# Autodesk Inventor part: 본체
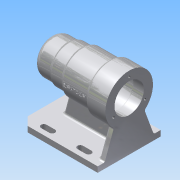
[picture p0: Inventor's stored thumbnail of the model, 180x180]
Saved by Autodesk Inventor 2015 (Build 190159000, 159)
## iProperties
Created: 2017-09
Part Number: 본체
Material: 알루미늄 6061
Document SubType Name: Modeling
Designer: Administrator
Density: 2.7 g/cm^3
Appearance: 알루미늄 - 평지
Author: Administrator
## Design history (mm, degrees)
sketch "스케치1"
  geometry: L1 (-133.636, 0)-(143, 0); L2 (112, 34)-(112, 0); L3 (112, 34)-(84, 34); L4 (84, 34)-(84, 30); L5 (84, 30)-(45, 30); L6 (45, 30)-(45, 27); L7 (45, 27)-(25, 27); L8 (0, 0)-(112, 0); L9 (25, 27)-(25, 25); L10 (25, 25)-(0, 25); L11 (0, 25)-(0, 0)
  constraints: 23 end point, 5 perpendicular, 3 horizontal, 3 vertical, 1 point on line
  dimensions: "d1" = 68 diameter of L3 L1; "d2" = 112 distance between parallel lines of L2 L11; "d3" = 60 diameter of L5 L1; "d4" = 54 diameter of L7 L1; "d5" = 50 diameter of L10 L1; "d6" = 84 distance between parallel lines of L4 L11; "d7" = 45 distance between parallel lines of L6 L11; "d8" = 25 distance between parallel lines of L9 L11
revolve "회전1" sketch "스케치1" stored, may be unused: angle "d9" = 90 deg
sketch "스케치2"
  geometry: L1 (0, -25)-(0, 25) reference; L2 (0, 25)-(25, 25) reference; L3 (25, 25)-(25, 27) reference; L4 (25, 27)-(45, 27) reference; L5 (45, 27)-(45, 30) reference; L6 (45, 30)-(84, 30) reference; L7 (84, 30)-(84, 34) reference; L8 (84, 34)-(112, 34) reference; L9 (112, 34)-(112, -34) reference; L10 (112, -34)-(84, -34) reference; L11 (84, -34)-(84, -30) reference; L12 (84, -30)-(45, -30) reference; L13 (45, -30)-(45, -27) reference; L14 (45, -27)-(25, -27) reference; L15 (25, -27)-(25, -25) reference; L16 (25, -25)-(0, -25) reference; L17 (-42, 0)-(152.04, 0); L18 (31, 17.5)-(31, 21); L19 (31, 21)-(43, 21); L20 (43, 21)-(43, 24); L21 (43, 24)-(97, 24); L22 (97, 24)-(97, 21); L23 (97, 21)-(112, 21); L24 (31, 17.5)-(13, 17.5); L25 (13, 17.5)-(13, 16); L26 (13, 16)-(9, 16); L27 (9, 16)-(9, 10.5); L28 (9, 10.5)-(6, 10.5); L29 (6, 10.5)-(6, 0); L30 (112, 21)-(112, 0); L31 (112, -34)-(112, 34) reference; L32 (6, 0)-(112, 0); 2 further points
  constraints: 30 end point, 9 perpendicular, 3 point on line, 3 vertical, 2 horizontal, 2 midpoint
  dimensions: "d10" = 42 diameter of L23 L17; "d11" = 15 distance of L22.end L23.end; "d12" = 48 diameter of L21 L17; "d13" = 54 distance of L20.end L21.end; "d14" = 42 diameter of L19 L17; "d15" = 12 distance between parallel lines of L20 L18; "d16" = 35 diameter of L24 L17; "d17" = 18 distance of L18.start L24.end; "d18" = 4 distance of L25.end L26.end; "d19" = 32 diameter of L26 L17; "d20" = 21 diameter of L28 L17; "d21" = 3 distance of L27.end L28.end
revolve "회전2" sketch "스케치2" stored, may be unused: angle "d22" = 90 deg
sketch "스케치3"
  geometry: L1 (-45, -62)-(45, -62); L2 (45, -62)-(45, -70); L3 (45, -70)-(-45, -70); L4 (-45, -70)-(-45, -62); C1 r 21 at (0, 0) reference; 1 further point
  constraints: 8 end point, 2 parallel, 1 horizontal, 1 midpoint, 1 perpendicular, 1 vertical alignment
  dimensions: "d23" = 8 distance between parallel lines of L3 L1; "d24" = 70 distance from line of L3 C1.centre; "d25" = 90 distance of L2.end L3.end
extrude "돌출1" join sketch "스케치3" distance "d26" = 112; taper "d27" = 0 deg
sketch "스케치4"
  geometry: L1 (21.067, -23.72)-(35.644, -63.77); L2 (35.644, -63.77)-(-35.644, -63.77); L3 (-35.644, -63.77)-(-21.067, -23.72); L4 (-21.067, -23.72)-(21.067, -23.72); L5 (-45, -62)-(45, -62) reference; L6 (-45, -70)-(-45, -62) reference; C1 r 21 at (0, 0) reference; 4 further points
  constraints: 8 end point, 4 point on line, 2 horizontal, 2 midpoint, 2 vertical alignment
  dimensions: "d28" = 110 deg angle of L5 L1; "d29" = 10 distance from line of L6 point (-35, -62)
extrude "돌출2" join sketch "스케치4" distance "d30" = 8; taper "d31" = 0 deg
sketch "스케치5"
  geometry: L1 (0, -25)-(0, 25) reference; L2 (0, 25)-(25, 25) reference; L3 (25, 25)-(25, 27) reference; L4 (25, 27)-(45, 27) reference; L5 (45, 27)-(45, 30) reference; L6 (45, 30)-(84, 30) reference; L7 (84, 30)-(84, 34) reference; L8 (84, 34)-(112, 34) reference; L9 (112, 34)-(112, 21) reference; L10 (112, 21)-(97, 21) reference; L11 (97, 21)-(97, 24) reference; L12 (97, 24)-(43, 24) reference; L13 (43, 24)-(43, 21) reference; L14 (43, 21)-(31, 21) reference; L15 (31, 21)-(31, 17.5) reference; L16 (31, 17.5)-(13, 17.5) reference; L17 (13, 17.5)-(13, 16) reference; L18 (13, 16)-(9, 16) reference; L19 (9, 16)-(9, 10.5) reference; L20 (9, 10.5)-(6, 10.5) reference; L21 (6, 10.5)-(6, -10.5) reference; L22 (6, -10.5)-(9, -10.5) reference; L23 (9, -10.5)-(9, -16) reference; L24 (9, -16)-(13, -16) reference; L25 (13, -16)-(13, -17.5) reference; L26 (13, -17.5)-(31, -17.5) reference; L27 (31, -17.5)-(31, -21) reference; L28 (31, -21)-(43, -21) reference; L29 (43, -21)-(43, -24) reference; L30 (43, -24)-(97, -24) reference; L31 (97, -24)-(97, -21) reference; L32 (97, -21)-(112, -21) reference; L33 (112, -21)-(112, -70) reference; L34 (112, -70)-(0, -70) reference; L35 (0, -70)-(0, -62) reference; L36 (0, -62)-(104, -62) reference; L37 (104, -62)-(104, -34) reference; L38 (104, -34)-(84, -34) reference; L39 (84, -34)-(84, -30) reference; L40 (84, -30)-(45, -30) reference; L41 (45, -30)-(45, -27) reference; L42 (45, -27)-(25, -27) reference; L43 (25, -27)-(25, -25) reference; L44 (25, -25)-(0, -25) reference; L45 (21.226, -64.887)-(31.878, -25.133); L46 (21.226, -64.887)-(107, -64.887); L47 (107, -64.887)-(107, -25.133); L48 (107, -25.133)-(31.878, -25.133); 2 further points
  constraints: 8 end point, 2 horizontal, 2 point on line, 1 vertical
  dimensions: "d32" = 105 deg angle of L45 L36; "d33" = 22 distance from line of L35 point (22, -62)
extrude "돌출3" join sketch "스케치5" stored distance "d34" = 8; taper "d35" = 0 deg
chamfer "모따기1" distance "d36" = 12; stored, may be unused: second distance "d37" = 2, angle "d38" = 45 deg
sketch "스케치6"
  geometry: L1 (0, 0)-(0, 10) reference; L2 (-88, 11)-(-76, 11); L3 (-88, 7)-(-76, 7); L4 (-76, 15)-(-88, 15); L5 (-36, 11)-(-24, 11); L6 (-36, 7)-(-24, 7); L7 (-24, 15)-(-36, 15); A1 r 4 centre (-88, 11) between (-88, 15) and (-88, 7); A2 r 4 centre (-76, 11) between (-76, 7) and (-76, 15); A3 r 4 centre (-36, 11) between (-36, 15) and (-36, 7); A4 r 4 centre (-24, 11) between (-24, 7) and (-24, 15); 3 further points
  constraints: 16 end point, 8 point on circle, 8 tangent, 4 centre point, 2 horizontal, 2 midpoint, 2 parallel, 1 horizontal alignment
  dimensions: "d39" = 4 radius of A1; "d40" = 12 distance of L2.start L2.end; "d41" = 34 distance from line of L2 point (-112, 45); "d42" = 12 distance of L5.start L5.end; "d43" = 4 radius of A3; "d44" = 24 distance from line of L1 L5.end; "d45" = 40 distance of L2.end L5.start
extrude "돌출4" cut sketch "스케치6" stored distance "d46" = 8; taper "d47" = 0 deg
fillet "모깎기1" dims "d48" = 9
fillet "모깎기2" dims "d49" = 3
fillet "모깎기3" dims "d50" = 0.3
fillet "모깎기4" dims "d51" = 3
fillet "모깎기5" dims "d52" = 3
sketch "스케치7"
  geometry: A1 r 34 centre (45, 70) between (66.9, 43.992) and (23.1, 43.992) reference; 1 further point
  constraints: 1 vertical alignment
  dimensions: "d53" = 26 distance of A1.centre point (45, 96)
hole "구멍1" sketch "스케치7" at (45, 96) diameter "d54" = 3.242; stored, may be unused: countersink angle "d58" = 90 deg, drill point angle "d60" = 118 deg; dims "d55" = 8, "d56" = 4, "d57" = 2, "d59" = 11
fillet "모깎기6" dims "d64" = 3
fillet "모깎기7" dims "d65" = 3
fillet "모깎기8" dims "d66" = 3
fillet "모깎기9" dims "d67" = 3
node "작업 평면1"
sketch "스케치8"
  geometry: L1 (47.196, -29.317)-(81, -29.317) reference; L2 (47.196, -29.317)-(47.196, -29.317) reference; L3 (81, -29.317)-(47.196, -29.317) reference; L4 (81, -29.317)-(81, -29.317) reference; L5 (86.657, -33.386)-(101, -33.386) reference; L6 (86.657, -33.386)-(86.657, -33.386) reference; L7 (101, -33.386)-(86.657, -33.386) reference; L8 (101, -28.328)-(101, -33.386) reference; L9 (112, -24.711)-(107, -24.711) reference; L10 (112, -24.711)-(112, -24.711) reference; L11 (107, -24.711)-(112, -24.711) reference; L12 (101, -33.386)-(101, -28.328) reference; L13 (112, -24.711)-(112, 34) reference; L14 (86.657, 34)-(112, 34) reference; L15 (47.196, 30)-(81, 30) reference; L16 (47.408, 2.402)-(80.592, 2.402); L17 (80.592, 2.402)-(80.592, -2.402); L18 (80.592, -2.402)-(47.408, -2.402); L19 (47.408, -2.402)-(47.408, 2.402); L20 (112, -70)-(12, -70) reference; 4 further points
  constraints: 2 midpoint, 1 horizontal alignment, 1 vertical alignment, 4 other
  dimensions: "d69" = 70 distance from line of point (64, 0) L20; "d70" = 48 distance from line of L13 point (64, 0)
feature "엠보싱1" sketch "스케치8" dims "d1" = 68, "d2" = 112, "d3" = 60, "d4" = 54, "d5" = 50, "d6" = 84, "d7" = 45, "d8" = 25, "d10" = 42, "d11" = 15, "d12" = 48, "d13" = 54, "d14" = 42, "d15" = 12, "d16" = 35, "d17" = 18, "d18" = 4, "d19" = 32, "d20" = 21, "d21" = 3, "d71" = 0.5, "d72" = 0
node "솔리드1"
mirror "대칭1"
pattern_circular "원형 패턴1" dims angle "d62" = 360 deg
node "투영된 루프1"
node "투영된 루프2"
node "절단 모서리 투영1"
node "절단 모서리 투영2"
other parameters: "d68" = 39.5
